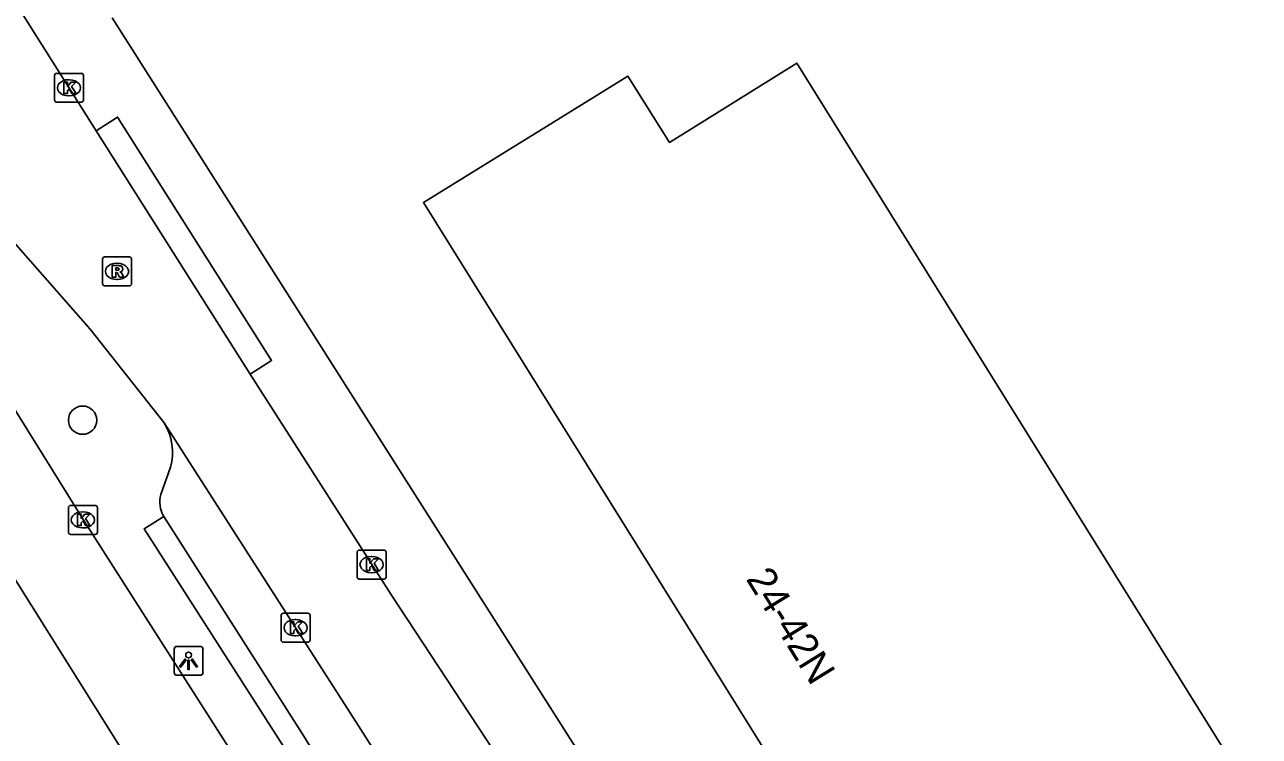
# Model space of a CAD drawing. Extents: x 160379 to 161131, y 383940 to 384849.
# Drawn here: x 160807.87 to 160850.55, y 384050.59 to 384075.18 of the extents above; entities that cross this region are included whole.
import ezdxf

# ---------------------------------------------------------------- set-up
doc = ezdxf.new("R2010")
doc.units = 0
for name, color, linetype in [('IMGEO_Boom', 7, 'Continuous'), ('IMGEO_Kolk', 7, 'Continuous'), ('IMGEO_Lichtpunt', 7, 'Continuous'), ('IMGEO_Pand', 7, 'Continuous'), ('IMGEO_Pand_nummerreeks', 7, 'Continuous'), ('IMGEO_Parkeervlak_open', 7, 'Continuous'), ('IMGEO_Rijbaan_lokaal_gesloten', 7, 'Continuous'), ('IMGEO_Rijbaan_lokaal_open', 7, 'Continuous'), ('IMGEO_Rioolput', 7, 'Continuous'), ('IMGEO_Voetpad_open', 7, 'Continuous')]:
    doc.layers.add(name, color=color, linetype=linetype)

msp = doc.modelspace()

# ---------------------------------------------------------------- linework, layer by layer
at = {"layer": 'IMGEO_Boom'}
msp.add_circle((160809.876, 384061.518), 0.489, dxfattribs=at)
at = {"layer": 'IMGEO_Kolk'}
for p, q in [((160808.905, 384072.575), (160808.905, 384073.427)), ((160808.98, 384073.501), (160809.832, 384073.501)), ((160809.393, 384073.281), (160809.418, 384073.281)), ((160809.906, 384073.427), (160809.906, 384072.575)), ((160809.416, 384072.721), (160809.391, 384072.721)), ((160809.832, 384072.501), (160808.98, 384072.501)), ((160809.384, 384057.647), (160809.384, 384058.499)), ((160809.459, 384058.573), (160810.311, 384058.573)), ((160809.872, 384058.353), (160809.897, 384058.353)), ((160810.385, 384058.499), (160810.385, 384057.647)), ((160809.895, 384057.793), (160809.87, 384057.793)), ((160810.311, 384057.573), (160809.459, 384057.573)), ((160819.363, 384056.101), (160819.363, 384056.953)), ((160819.438, 384057.027), (160820.29, 384057.027)), ((160820.364, 384056.953), (160820.364, 384056.101)), ((160819.851, 384056.807), (160819.876, 384056.807)), ((160820.29, 384056.027), (160819.438, 384056.027)), ((160819.874, 384056.247), (160819.849, 384056.247)), ((160816.737, 384053.921), (160816.737, 384054.773)), ((160816.812, 384054.847), (160817.664, 384054.847)), ((160817.738, 384054.773), (160817.738, 384053.921)), ((160817.225, 384054.627), (160817.25, 384054.627)), ((160817.248, 384054.067), (160817.223, 384054.067)), ((160817.664, 384053.847), (160816.812, 384053.847))]:
    msp.add_line(p, q, dxfattribs=at)
for points in [[(160808.905, 384072.575), (160808.905, 384073.427)], [(160808.98, 384073.501), (160809.832, 384073.501)], [(160809.226, 384073.201), (160809.349, 384073.201), (160809.349, 384073.05), (160809.479, 384073.201), (160809.643, 384073.201), (160809.497, 384073.05), (160809.65, 384072.801), (160809.498, 384072.801), (160809.413, 384072.965), (160809.349, 384072.898), (160809.349, 384072.801), (160809.226, 384072.801), (160809.226, 384073.201)], [(160809.906, 384073.427), (160809.906, 384072.575)], [(160809.832, 384072.501), (160808.98, 384072.501)], [(160809.384, 384057.647), (160809.384, 384058.499)], [(160809.459, 384058.573), (160810.311, 384058.573)], [(160809.705, 384058.273), (160809.828, 384058.273), (160809.828, 384058.122), (160809.958, 384058.273), (160810.122, 384058.273), (160809.976, 384058.122), (160810.129, 384057.873), (160809.977, 384057.873), (160809.892, 384058.037), (160809.828, 384057.97), (160809.828, 384057.873), (160809.705, 384057.873), (160809.705, 384058.273)], [(160810.385, 384058.499), (160810.385, 384057.647)], [(160810.311, 384057.573), (160809.459, 384057.573)], [(160819.363, 384056.101), (160819.363, 384056.953)], [(160819.438, 384057.027), (160820.29, 384057.027)], [(160820.364, 384056.953), (160820.364, 384056.101)], [(160819.684, 384056.727), (160819.807, 384056.727), (160819.807, 384056.576), (160819.937, 384056.727), (160820.101, 384056.727), (160819.955, 384056.576), (160820.108, 384056.327), (160819.956, 384056.327), (160819.871, 384056.491), (160819.807, 384056.424), (160819.807, 384056.327), (160819.684, 384056.327), (160819.684, 384056.727)], [(160820.29, 384056.027), (160819.438, 384056.027)], [(160816.737, 384053.921), (160816.737, 384054.773)], [(160816.812, 384054.847), (160817.664, 384054.847)], [(160817.738, 384054.773), (160817.738, 384053.921)], [(160817.058, 384054.547), (160817.181, 384054.547), (160817.181, 384054.396), (160817.311, 384054.547), (160817.475, 384054.547), (160817.329, 384054.396), (160817.482, 384054.147), (160817.33, 384054.147), (160817.245, 384054.311), (160817.181, 384054.244), (160817.181, 384054.147), (160817.058, 384054.147), (160817.058, 384054.547)], [(160817.664, 384053.847), (160816.812, 384053.847)]]:
    msp.add_lwpolyline(points, dxfattribs=at)
for centre, start, end in [((160808.982, 384073.425), 91.552, 178.448), ((160808.982, 384073.425), 91.552, 178.448), ((160809.83, 384073.425), 1.552, 88.448), ((160809.83, 384073.425), 1.552, 88.448), ((160808.982, 384072.577), 181.552, 268.448), ((160808.982, 384072.577), 181.552, 268.448), ((160809.83, 384072.577), 271.552, 358.448), ((160809.83, 384072.577), 271.552, 358.448), ((160809.461, 384058.497), 91.552, 178.448), ((160809.461, 384058.497), 91.552, 178.448), ((160810.309, 384058.497), 1.552, 88.448), ((160810.309, 384058.497), 1.552, 88.448), ((160809.461, 384057.649), 181.552, 268.448), ((160809.461, 384057.649), 181.552, 268.448), ((160810.309, 384057.649), 271.552, 358.448), ((160810.309, 384057.649), 271.552, 358.448), ((160819.44, 384056.951), 91.552, 178.448), ((160819.44, 384056.951), 91.552, 178.448), ((160820.288, 384056.951), 1.552, 88.448), ((160820.288, 384056.951), 1.552, 88.448), ((160819.44, 384056.103), 181.552, 268.448), ((160819.44, 384056.103), 181.552, 268.448), ((160820.288, 384056.103), 271.552, 358.448), ((160820.288, 384056.103), 271.552, 358.448), ((160816.814, 384054.771), 91.552, 178.448), ((160816.814, 384054.771), 91.552, 178.448), ((160817.662, 384054.771), 1.552, 88.448), ((160817.662, 384054.771), 1.552, 88.448), ((160816.814, 384053.923), 181.552, 268.448), ((160816.814, 384053.923), 181.552, 268.448), ((160817.662, 384053.923), 271.552, 358.448), ((160817.662, 384053.923), 271.552, 358.448)]:
    msp.add_arc(centre, 0.0765, start, end, dxfattribs=at)
for centre, major_axis, ratio, start_param, end_param in [((160809.392, 384073.001), (-0.387, 0.002), 0.722429, 4.712389, 7.853982), ((160809.417, 384073.001), (-0.39, 0.002), 0.717154, 1.570796, 4.712389), ((160809.871, 384058.073), (-0.387, 0.002), 0.722429, 4.712389, 7.853982), ((160809.896, 384058.073), (-0.39, 0.002), 0.717154, 1.570796, 4.712389), ((160819.85, 384056.527), (-0.387, 0.002), 0.722429, 4.712389, 7.853982), ((160819.875, 384056.527), (-0.39, 0.002), 0.717154, 1.570796, 4.712389), ((160817.224, 384054.347), (-0.387, 0.002), 0.722429, 4.712389, 7.853982), ((160817.249, 384054.347), (-0.39, 0.002), 0.717154, 1.570796, 4.712389)]:
    msp.add_ellipse(centre, major_axis=major_axis, ratio=ratio, start_param=start_param, end_param=end_param, dxfattribs=at)
at = {"layer": 'IMGEO_Lichtpunt'}
for p, q in [((160813.041, 384053.606), (160813.041, 384052.799)), ((160813.041, 384053.606), (160813.041, 384052.799)), ((160813.943, 384053.701), (160813.135, 384053.701)), ((160813.943, 384053.701), (160813.135, 384053.701)), ((160814.037, 384052.799), (160814.037, 384053.606)), ((160814.037, 384052.799), (160814.037, 384053.606)), ((160813.135, 384052.705), (160813.943, 384052.705)), ((160813.135, 384052.705), (160813.943, 384052.705))]:
    msp.add_line(p, q, dxfattribs=at)
for points in [[(160813.415, 384053.27), (160813.454, 384053.242), (160813.266, 384052.98), (160813.228, 384053.007), (160813.415, 384053.27)], [(160813.517, 384053.222), (160813.564, 384053.222), (160813.564, 384052.9), (160813.517, 384052.9), (160813.517, 384053.222)], [(160813.627, 384053.242), (160813.665, 384053.269), (160813.852, 384053.007), (160813.813, 384052.979), (160813.627, 384053.242)]]:
    msp.add_lwpolyline(points, dxfattribs=at)
msp.add_circle((160813.54, 384053.404), 0.0994, dxfattribs=at)
for centre, start, end in [((160813.135, 384053.606), 90, 180), ((160813.135, 384053.606), 90, 180), ((160813.943, 384053.606), 0, 90), ((160813.943, 384053.606), 0, 90), ((160813.135, 384052.799), 180, 270), ((160813.135, 384052.799), 180, 270), ((160813.943, 384052.799), 270, 0), ((160813.943, 384052.799), 270, 360)]:
    msp.add_arc(centre, 0.0946, start, end, dxfattribs=at)
at = {"layer": 'IMGEO_Pand'}
msp.add_lwpolyline([(160865.023, 384046.232), (160858.528, 384042.194), (160860.904, 384038.386), (160856.823, 384035.82), (160852.59, 384033.159), (160846.415, 384029.308), (160842.556, 384035.497), (160821.656, 384069.036), (160825.909, 384071.667), (160828.723, 384073.409), (160830.164, 384071.117), (160834.558, 384073.858), (160849.721, 384049.496), (160852.429, 384051.192), (160851.059, 384053.378), (160857.909, 384057.668), (160865.023, 384046.232)], dxfattribs=at)
at = {"layer": 'IMGEO_Parkeervlak_open'}
msp.add_lwpolyline([(160812.581, 384058.952), (160812.918, 384059.892)], dxfattribs=at)
for centre, radius, start, end in [((160810.993, 384060.394), 1.989, 345.3915, 31.4003), ((160813.574, 384058.692), 1.027, 165.3075, 209.549)]:
    msp.add_arc(centre, radius, start, end, dxfattribs=at)
at = {"layer": 'IMGEO_Rijbaan_lokaal_gesloten'}
for points in [[(160882.487, 383957.728), (160854.954, 383990.458), (160837.19, 384012.568), (160828.849, 384023.623), (160817.937, 384039.793), (160814.718, 384044.564), (160806.475, 384057.701), (160799.553, 384068.733), (160788.358, 384088.753), (160780.528, 384102.757), (160774.602, 384112.332), (160771.363, 384117.566)], [(160817.58, 384046.047), (160809.892, 384058.082), (160804.996, 384065.946), (160802.895, 384069.303)]]:
    msp.add_lwpolyline(points, dxfattribs=at)
at = {"layer": 'IMGEO_Rijbaan_lokaal_open'}
for points in [[(160801.966, 384084.783), (160810.34, 384071.52)], [(160815.664, 384063.109), (160810.34, 384071.52)], [(160812.691, 384061.43), (160810.137, 384064.666), (160805.922, 384069.453), (160804.909, 384070.605)], [(160815.664, 384063.109), (160820.547, 384055.466), (160829.481, 384041.892), (160840.039, 384027.278)], [(160812.691, 384061.43), (160819.416, 384050.957)]]:
    msp.add_lwpolyline(points, dxfattribs=at)
msp.add_arc((161100.524, 384226.279), 331.299, 211.95105, 216.92054, dxfattribs=at)
at = {"layer": 'IMGEO_Rioolput'}
for p, q in [((160810.641, 384067.159), (160811.493, 384067.159)), ((160810.566, 384066.233), (160810.566, 384067.085)), ((160811.054, 384066.939), (160811.079, 384066.939)), ((160811.567, 384067.085), (160811.567, 384066.233)), ((160811.077, 384066.379), (160811.052, 384066.379)), ((160811.493, 384066.159), (160810.641, 384066.159))]:
    msp.add_line(p, q, dxfattribs=at)
for points in [[(160810.641, 384067.159), (160811.493, 384067.159)], [(160810.566, 384066.233), (160810.566, 384067.085)], [(160811.155, 384066.857), (160810.903, 384066.859), (160810.903, 384066.459)], [(160811.081, 384066.778), (160811.027, 384066.778), (160811.027, 384066.697)], [(160811.027, 384066.697), (160811.079, 384066.697)], [(160811.567, 384067.085), (160811.567, 384066.233)], [(160810.903, 384066.459), (160811.027, 384066.459), (160811.027, 384066.621), (160811.038, 384066.621)], [(160811.085, 384066.592), (160811.156, 384066.459), (160811.296, 384066.459), (160811.231, 384066.585)], [(160811.493, 384066.159), (160810.641, 384066.159)]]:
    msp.add_lwpolyline(points, dxfattribs=at)
for centre, radius, start, end in [((160810.643, 384067.083), 0.0765, 91.552, 178.448), ((160810.643, 384067.083), 0.0765, 91.552, 178.448), ((160811.491, 384067.083), 0.0765, 1.552, 88.448), ((160811.491, 384067.083), 0.0765, 1.552, 88.448), ((160811.063, 384066.886), 0.19, 274.7715, 282.9687), ((160811.087, 384066.682), 0.0964, 77.0061, 93.1865), ((160811.101, 384066.739), 0.0378, 276.6634, 79.6772), ((160811.154, 384066.747), 0.109, 350.3612, 89.416), ((160811.152, 384066.747), 0.112, 277.5842, 350.9817), ((160811.037, 384066.568), 0.0533, 26.0293, 88.6989), ((160811.136, 384066.532), 0.108, 29.5134, 73.7905), ((160810.643, 384066.235), 0.0765, 181.552, 268.448), ((160810.643, 384066.235), 0.0765, 181.552, 268.448), ((160811.491, 384066.235), 0.0765, 271.552, 358.448), ((160811.491, 384066.235), 0.0765, 271.552, 358.448)]:
    msp.add_arc(centre, radius, start, end, dxfattribs=at)
for centre, major_axis, ratio, start_param, end_param in [((160811.053, 384066.659), (-0.387, 0.002), 0.722429, 4.712389, 7.853982), ((160811.078, 384066.659), (-0.39, 0.002), 0.717154, 1.570796, 4.712389)]:
    msp.add_ellipse(centre, major_axis=major_axis, ratio=ratio, start_param=start_param, end_param=end_param, dxfattribs=at)
at = {"layer": 'IMGEO_Voetpad_open'}
for points in [[(160810.903, 384075.416), (160826.814, 384050.384), (160839.008, 384032.761), (160850.763, 384017.327), (160864.866, 384000), (160884.176, 383976.276)], [(160810.34, 384071.52), (160811.084, 384071.991), (160816.406, 384063.584), (160815.664, 384063.109)], [(160818.91, 384046.954), (160818.774, 384047.165), (160818.366, 384047.804), (160817.615, 384048.987), (160816.869, 384050.174), (160812.001, 384057.76), (160812.681, 384058.185)], [(160817.519, 384050.595), (160812.681, 384058.185)]]:
    msp.add_lwpolyline(points, dxfattribs=at)
msp.add_arc((161126.395, 384245.165), 365.05, 212.20811, 216.45318, dxfattribs=at)

# ---------------------------------------------------------------- texts
at = {"layer": 'IMGEO_Pand_nummerreeks'}
msp.add_text('24-42N', height=1, rotation=301.6779, dxfattribs=at).set_placement((160832.783, 384056.032))

doc.saveas('drawing.dxf')
